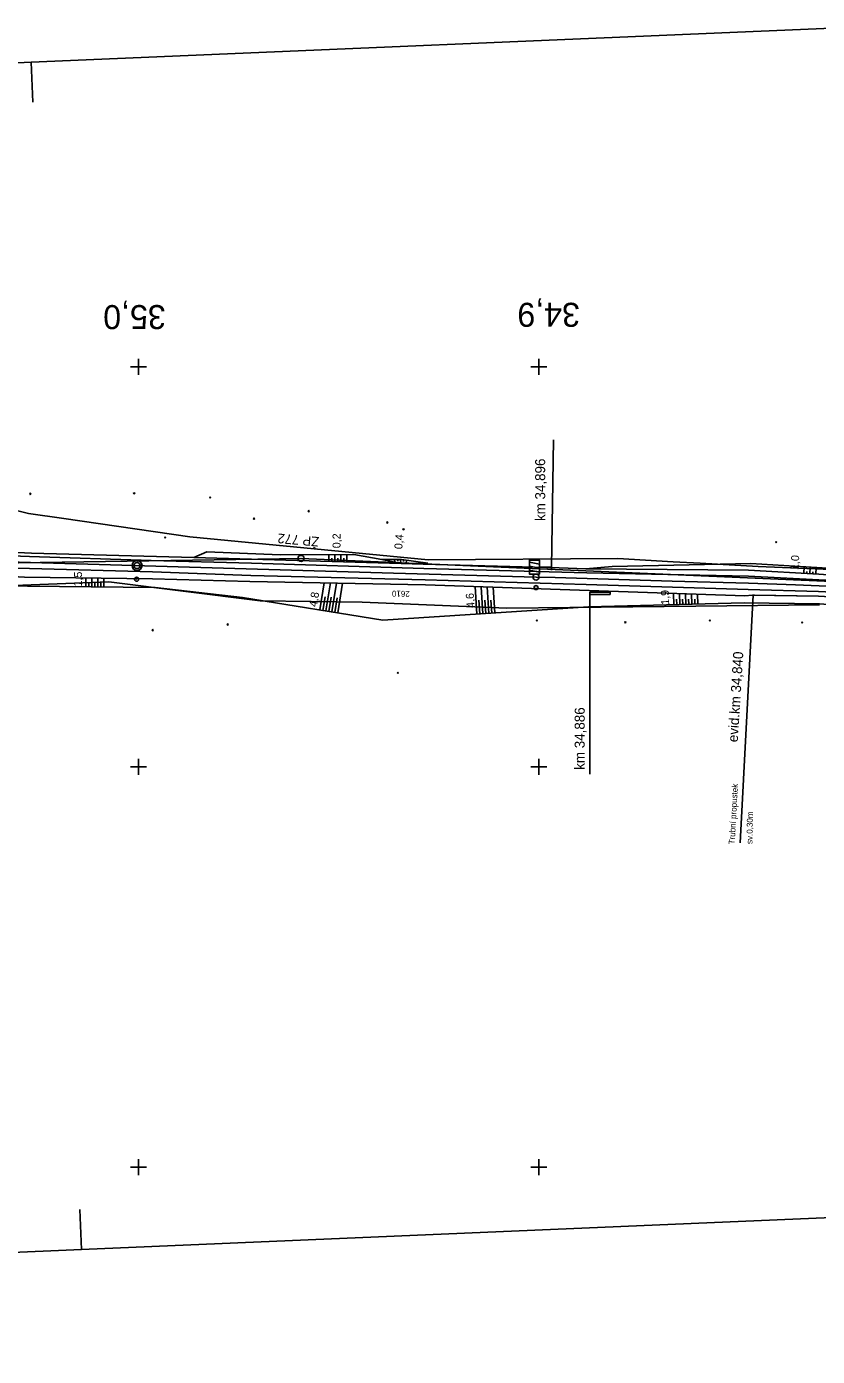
# Model space of a CAD drawing. Extents: x -806456 to -805395, y -1150847 to -1150506.
# Drawn here: x -805828 to -805630.4, y -1150847.3 to -1150515 of the extents above; entities that cross this region are included whole.
import ezdxf

# ---------------------------------------------------------------- set-up
doc = ezdxf.new("R2010")
doc.units = 0
for name, color, linetype in [('0381KM032-037P - Vrstva 1', 7, 'Continuous'), ('0381KM032-037P - Vrstva 19', 7, 'Continuous'), ('0381KM032-037P - Vrstva 4', 7, 'Continuous'), ('0381KM032-037P - Vrstva 48', 7, 'Continuous'), ('0381KM032-037P - Vrstva 49', 7, 'Continuous'), ('0381KM032-037P - Vrstva 57', 7, 'Continuous'), ('0381KM032-037P - Vrstva 7', 7, 'Continuous'), ('0381KM032-037P - Vrstva 9', 7, 'Continuous'), ('formát', 7, 'Continuous'), ('hran DP - hran DP', 7, 'Continuous'), ('krizky_1000 - Vrstva 1', 7, 'Continuous'), ('vyt_sit - polygon', 7, 'Continuous'), ('vyt_sit - stávající', 7, 'Continuous')]:
    doc.layers.add(name, color=color, linetype=linetype)

msp = doc.modelspace()

# ---------------------------------------------------------------- linework, layer by layer
at = {"layer": '0381KM032-037P - Vrstva 1'}
for points in [[(-805647.61, -1150654.06), (-805666.7, -1150653.55), (-805695.88, -1150652.69), (-805700.7, -1150652.54), (-805736.3, -1150651.55), (-805773.14, -1150650.48), (-805809.82, -1150649.4), (-805847.04, -1150648.36), (-805872.37, -1150647.65)], [(-805607.93, -1150656.05), (-805622.11, -1150655.05), (-805635.9, -1150654.45), (-805647.61, -1150654.06)]]:
    msp.add_lwpolyline(points, dxfattribs=at)
at = {"layer": '0381KM032-037P - Vrstva 19'}
for p, q in [((-805646.42, -1150657.11), (-805649.68, -1150718.98)), ((-805646.66, -1150657.1), (-805646.15, -1150657.11))]:
    msp.add_line(p, q, dxfattribs=at)
for points in [[(-805646.66, -1150657.1), (-805646.66, -1150657.1), (-805646.57, -1150657.13)], [(-805646.27, -1150657.1), (-805646.15, -1150657.11), (-805646.15, -1150657.11)]]:
    msp.add_lwpolyline(points, dxfattribs=at)
msp.add_ellipse((-805646.42, -1150657.11), major_axis=(0.15, 0.019), ratio=0.46044, start_param=6.207328, end_param=9.448235, dxfattribs=at)
at = {"layer": '0381KM032-037P - Vrstva 4'}
msp.add_line((-805728.9, -1150649.35), (-805734.36, -1150649.18), dxfattribs=at)
for points in [[(-805734.36, -1150649.18), (-805786.14, -1150647.68), (-805826.72, -1150646.54), (-805841.05, -1150645.92), (-805859.62, -1150645.3), (-805883.54, -1150644.38), (-805898.84, -1150644.02), (-805920.59, -1150645.08)], [(-805687.98, -1150651.47), (-805728.71, -1150650.4), (-805771.75, -1150649.09), (-805796.82, -1150648.44), (-805827.25, -1150647.42), (-805868.08, -1150645.94), (-805883.57, -1150645.79), (-805899.1, -1150645.56), (-805920.66, -1150646.24), (-805923.83, -1150646.61)], [(-805688.15, -1150654.42), (-805728.36, -1150653.2), (-805771.94, -1150652.19), (-805796.53, -1150651.28), (-805827.23, -1150650.42), (-805883.58, -1150648.86), (-805898.54, -1150648.68), (-805920.02, -1150649.65), (-805923.42, -1150649.97)], [(-805687.42, -1150655.93), (-805728.29, -1150654.47), (-805772.22, -1150653.64), (-805796.51, -1150653.02), (-805828.44, -1150652.6), (-805870.39, -1150650.22), (-805873.51, -1150650.39), (-805883.54, -1150650.55), (-805898.37, -1150650.08), (-805919.92, -1150650.63), (-805923.37, -1150650.9)], [(-805688.26, -1150650.5), (-805694.92, -1150650.2), (-805728.9, -1150649.35)], [(-805485.85, -1150681.76), (-805498.96, -1150678.92), (-805510.6, -1150675.66), (-805525.22, -1150671.48), (-805544.53, -1150665.72), (-805562.31, -1150661.11), (-805574.56, -1150658.15), (-805590.74, -1150655.42), (-805602.22, -1150654.14), (-805617.62, -1150652.74), (-805630.08, -1150651.83), (-805647.65, -1150650.8), (-805688.26, -1150650.5)], [(-805423.97, -1150686.92), (-805425.51, -1150687.49), (-805433.17, -1150688.49), (-805447.58, -1150687.79), (-805460.54, -1150686.52), (-805473.03, -1150684.97), (-805486, -1150682.53), (-805499.06, -1150679.64), (-805510.93, -1150676.58), (-805525.41, -1150672.29), (-805545.14, -1150666.47), (-805562.36, -1150661.85), (-805574.71, -1150659.28), (-805590.7, -1150656.46), (-805602.42, -1150654.96), (-805617.57, -1150653.8), (-805630.08, -1150653.28), (-805647.6, -1150652.35), (-805687.98, -1150651.47)], [(-805425.98, -1150691.47), (-805433.13, -1150691.22), (-805447.47, -1150690.71), (-805460.74, -1150689.57), (-805473.54, -1150687.87), (-805486.2, -1150685.62), (-805499.7, -1150682.42), (-805511.82, -1150679.35), (-805526.11, -1150675.23), (-805545.84, -1150669.48), (-805563.16, -1150664.96), (-805575.57, -1150662.2), (-805590.62, -1150659.46), (-805602.86, -1150658.06), (-805617.64, -1150656.78), (-805630.16, -1150656.16), (-805647.73, -1150655.65), (-805688.15, -1150654.42)], [(-805425.41, -1150692.47), (-805425.98, -1150691.47), (-805433.11, -1150692.35), (-805447.61, -1150691.82), (-805460.9, -1150690.59), (-805473.67, -1150688.98), (-805486.26, -1150686.57), (-805500.08, -1150683.65), (-805512.15, -1150680.12), (-805526.27, -1150676.26), (-805545.98, -1150670.57), (-805563.42, -1150665.87), (-805575.79, -1150663.12), (-805590.93, -1150660.59), (-805603.28, -1150659.09), (-805617.92, -1150657.97), (-805630.11, -1150657.32), (-805646.66, -1150657.1), (-805648.58, -1150657.2), (-805687.42, -1150655.93)]]:
    msp.add_lwpolyline(points, dxfattribs=at)
at = {"layer": '0381KM032-037P - Vrstva 48'}
for p, q in [((-805752.48, -1150648.66), (-805752.44, -1150646.97)), ((-805750.98, -1150648.7), (-805750.94, -1150646.96)), ((-805749.49, -1150648.74), (-805749.43, -1150646.96)), ((-805747.99, -1150648.79), (-805747.93, -1150646.95)), ((-805751.73, -1150648.68), (-805751.71, -1150647.82)), ((-805750.24, -1150648.72), (-805750.21, -1150647.84)), ((-805748.74, -1150648.77), (-805748.71, -1150647.86)), ((-805736.02, -1150648.12), (-805736.01, -1150648.83)), ((-805735.27, -1150648.12), (-805735.26, -1150648.56)), ((-805734.52, -1150648.12), (-805734.51, -1150649.15)), ((-805733.77, -1150648.2), (-805733.84, -1150648.69)), ((-805733.03, -1150648.31), (-805733.15, -1150649.17)), ((-805633.83, -1150651.61), (-805633.73, -1150649.96)), ((-805632.33, -1150651.7), (-805632.24, -1150650.05)), ((-805630.84, -1150651.79), (-805630.74, -1150650.15)), ((-805813.18, -1150654.95), (-805813.15, -1150652.8)), ((-805812.43, -1150654.96), (-805812.41, -1150653.89)), ((-805811.68, -1150654.97), (-805811.65, -1150652.82)), ((-805810.93, -1150654.98), (-805810.91, -1150653.91)), ((-805810.18, -1150654.99), (-805810.15, -1150652.84)), ((-805809.43, -1150654.99), (-805809.41, -1150653.92)), ((-805808.68, -1150655), (-805808.65, -1150652.86)), ((-805754.68, -1150660.78), (-805753.59, -1150653.99)), ((-805753.2, -1150661.01), (-805752.08, -1150654.02)), ((-805751.72, -1150661.25), (-805750.56, -1150654.05)), ((-805750.24, -1150661.49), (-805749.05, -1150654.08)), ((-805633.08, -1150651.65), (-805633.05, -1150651.16)), ((-805631.59, -1150651.74), (-805631.56, -1150651.25)), ((-805715.49, -1150661.81), (-805715.93, -1150654.91)), ((-805713.99, -1150661.71), (-805714.42, -1150654.97)), ((-805712.5, -1150661.62), (-805712.92, -1150655.02)), ((-805711, -1150661.52), (-805711.41, -1150655.07)), ((-805666.28, -1150659.46), (-805666.35, -1150656.62)), ((-805664.78, -1150659.42), (-805664.85, -1150656.67)), ((-805663.28, -1150659.38), (-805663.35, -1150656.72)), ((-805661.78, -1150659.34), (-805661.85, -1150656.77)), ((-805660.28, -1150659.3), (-805660.35, -1150656.81)), ((-805753.94, -1150660.89), (-805753.39, -1150657.45)), ((-805752.46, -1150661.13), (-805751.89, -1150657.58)), ((-805750.98, -1150661.37), (-805750.39, -1150657.72)), ((-805714.74, -1150661.76), (-805714.96, -1150658.35)), ((-805713.24, -1150661.67), (-805713.46, -1150658.33)), ((-805711.75, -1150661.57), (-805711.96, -1150658.31)), ((-805665.53, -1150659.44), (-805665.57, -1150658.04)), ((-805664.03, -1150659.4), (-805664.07, -1150658.04)), ((-805662.53, -1150659.36), (-805662.57, -1150658.05)), ((-805661.03, -1150659.32), (-805661.07, -1150658.05))]:
    msp.add_line(p, q, dxfattribs=at)
at = {"layer": '0381KM032-037P - Vrstva 49'}
for p, q in [((-805827.2, -1150631.55), (-805826.85, -1150631.9)), ((-805827.2, -1150631.9), (-805826.85, -1150631.55)), ((-805801.28, -1150631.44), (-805800.93, -1150631.8)), ((-805801.28, -1150631.8), (-805800.93, -1150631.44)), ((-805782.28, -1150632.48), (-805781.92, -1150632.83)), ((-805782.28, -1150632.83), (-805781.92, -1150632.48)), ((-805757.67, -1150635.89), (-805757.32, -1150636.25)), ((-805757.67, -1150636.25), (-805757.32, -1150635.89)), ((-805770.97, -1150637.78), (-805771.33, -1150638.14)), ((-805771.33, -1150637.78), (-805770.97, -1150638.13)), ((-805738.02, -1150638.73), (-805737.67, -1150639.09)), ((-805738.02, -1150639.09), (-805737.67, -1150638.73)), ((-805733.63, -1150640.45), (-805733.99, -1150640.81)), ((-805733.99, -1150640.45), (-805733.63, -1150640.81)), ((-805793.18, -1150642.5), (-805793.53, -1150642.85)), ((-805793.53, -1150642.5), (-805793.18, -1150642.85)), ((-805640.56, -1150643.67), (-805640.92, -1150644.02)), ((-805640.92, -1150643.67), (-805640.56, -1150644.02)), ((-805700.33, -1150663.23), (-805700.68, -1150663.59)), ((-805700.68, -1150663.23), (-805700.33, -1150663.58)), ((-805678.21, -1150663.68), (-805678.56, -1150664.04)), ((-805678.56, -1150663.69), (-805678.21, -1150664.04)), ((-805657.1, -1150663.22), (-805657.46, -1150663.57)), ((-805657.46, -1150663.22), (-805657.1, -1150663.57)), ((-805634.06, -1150663.7), (-805634.41, -1150664.05)), ((-805634.41, -1150663.7), (-805634.05, -1150664.05)), ((-805796.29, -1150665.66), (-805796.64, -1150666.01)), ((-805796.64, -1150665.66), (-805796.29, -1150666.01)), ((-805777.92, -1150664.26), (-805777.56, -1150664.61)), ((-805777.56, -1150664.26), (-805777.91, -1150664.61)), ((-805735.04, -1150676.33), (-805735.39, -1150676.68)), ((-805735.39, -1150676.33), (-805735.04, -1150676.68))]:
    msp.add_line(p, q, dxfattribs=at)
for points in [[(-805786.14, -1150647.68), (-805826.72, -1150646.54), (-805841.05, -1150645.92)], [(-805786.14, -1150647.68), (-805782.97, -1150646.21), (-805764.63, -1150647), (-805746.23, -1150646.95), (-805739.21, -1150648.13), (-805734.36, -1150649.18), (-805727.71, -1150649.08)], [(-805687.42, -1150655.93), (-805728.29, -1150654.47), (-805772.22, -1150653.64), (-805796.51, -1150653.02), (-805828.44, -1150652.6), (-805870.39, -1150650.22)], [(-805687.58, -1150660.02), (-805738.95, -1150663.31), (-805774.06, -1150657.65), (-805795.8, -1150655.14), (-805835.84, -1150654.7), (-805870.36, -1150656.71), (-805870.39, -1150650.22)], [(-805734.36, -1150649.18), (-805786.14, -1150647.68)], [(-805727.71, -1150649.08), (-805734.34, -1150648.12), (-805739.21, -1150648.13)], [(-805602.19, -1150651.94), (-805630.54, -1150650.16), (-805647.04, -1150649.14), (-805681.66, -1150649.9), (-805688.26, -1150650.5)], [(-805423.97, -1150686.92), (-805433.1, -1150687.91), (-805447.34, -1150686.91), (-805460.49, -1150686.09), (-805485.85, -1150681.76), (-805498.96, -1150678.92), (-805510.6, -1150675.66), (-805525.22, -1150671.48), (-805544.53, -1150665.72), (-805562.31, -1150661.11), (-805571.99, -1150658.79), (-805574.56, -1150658.15), (-805590.74, -1150655.42), (-805602.22, -1150654.14), (-805617.62, -1150652.74), (-805630.08, -1150651.83), (-805647.65, -1150650.8), (-805688.26, -1150650.5)], [(-805425.41, -1150692.47), (-805425.98, -1150691.47), (-805433.11, -1150692.35), (-805447.61, -1150691.82), (-805460.9, -1150690.59), (-805473.67, -1150688.98), (-805486.26, -1150686.57), (-805500.08, -1150683.65), (-805512.15, -1150680.12), (-805526.27, -1150676.26), (-805545.98, -1150670.57), (-805563.42, -1150665.87), (-805575.79, -1150663.12), (-805590.93, -1150660.59), (-805603.28, -1150659.09), (-805617.92, -1150657.97), (-805630.11, -1150657.32), (-805646.15, -1150657.11), (-805646.27, -1150657.1), (-805646.57, -1150657.13), (-805646.66, -1150657.1), (-805648.58, -1150657.2), (-805687.42, -1150655.93)], [(-805428.8, -1150698.61), (-805426.99, -1150695.45), (-805434.79, -1150695.76), (-805452.59, -1150694.8), (-805474.79, -1150691.73), (-805486.9, -1150690.07), (-805513.13, -1150683.83), (-805526.69, -1150679.91), (-805538.18, -1150675.92), (-805547.05, -1150672.92), (-805563.97, -1150668.42), (-805576.87, -1150665.35), (-805586.81, -1150663.24), (-805590.73, -1150662.74), (-805601.92, -1150661.35), (-805629.88, -1150659.22), (-805648.74, -1150658.99), (-805687.58, -1150660.02)]]:
    msp.add_lwpolyline(points, dxfattribs=at)
at = {"layer": '0381KM032-037P - Vrstva 7'}
for p, q in [((-805696.85, -1150650.05), (-805696.3, -1150618.26)), ((-805699.85, -1150649.3), (-805702.35, -1150648.8)), ((-805702.35, -1150649.8), (-805699.85, -1150650.3)), ((-805696.85, -1150650.8), (-805696.85, -1150649.3)), ((-805800.52, -1150653.09), (-805800.42, -1150653.09)), ((-805699.85, -1150651.3), (-805702.35, -1150650.8)), ((-805700.75, -1150655.18), (-805700.65, -1150655.18))]:
    msp.add_line(p, q, dxfattribs=at)
msp.add_lwpolyline([(-805696.85, -1150650.05), (-805699.85, -1150650.05), (-805699.85, -1150648.3), (-805702.35, -1150648.3), (-805702.35, -1150651.8), (-805699.85, -1150651.8), (-805699.85, -1150650.05)], dxfattribs=at)
for centre, radius in [((-805800.37, -1150649.68), 1.25), ((-805800.37, -1150649.68), 0.752), ((-805800.47, -1150653.09), 0.5), ((-805700.7, -1150652.54), 0.75), ((-805700.7, -1150655.18), 0.5)]:
    msp.add_circle(centre, radius, dxfattribs=at)
at = {"layer": '0381KM032-037P - Vrstva 9'}
for p, q in [((-805682.22, -1150656.32), (-805687.22, -1150656.31)), ((-805687.22, -1150656.31), (-805687.22, -1150656.91)), ((-805687.22, -1150656.61), (-805687.22, -1150701.82)), ((-805687.22, -1150656.91), (-805682.22, -1150656.92)), ((-805687.22, -1150656.91), (-805687.22, -1150657.51)), ((-805682.22, -1150656.92), (-805682.22, -1150656.32))]:
    msp.add_line(p, q, dxfattribs=at)
at = {"layer": 'formát'}
for p, q in [((-805617.02, -1150514.97), (-805826.83, -1150523.88)), ((-805826.83, -1150523.88), (-806456.26, -1150550.6)), ((-805826.83, -1150523.88), (-805826.4, -1150533.87)), ((-805814.66, -1150810.62), (-805814.23, -1150820.61)), ((-805604.42, -1150811.7), (-805814.23, -1150820.61)), ((-805814.23, -1150820.61), (-806443.66, -1150847.33))]:
    msp.add_line(p, q, dxfattribs=at)
at = {"layer": 'hran DP - hran DP'}
for p, q in [((-805845.04, -1150632.24), (-805827.46, -1150636.65)), ((-805827.46, -1150636.65), (-805818.65, -1150637.92)), ((-805818.65, -1150637.92), (-805787.18, -1150642.48)), ((-805787.18, -1150642.48), (-805727.67, -1150648.26)), ((-805727.67, -1150648.26), (-805680.28, -1150647.93)), ((-805680.28, -1150647.93), (-805666.44, -1150648.72)), ((-805666.44, -1150648.72), (-805659.71, -1150649.1)), ((-805659.71, -1150649.1), (-805655.39, -1150649.35)), ((-805655.39, -1150649.35), (-805645.21, -1150649.93)), ((-805645.21, -1150649.93), (-805611.34, -1150651.29)), ((-805807.41, -1150653.77), (-805838.22, -1150654.94)), ((-805769.65, -1150658.51), (-805807.41, -1150653.77)), ((-805744.09, -1150658.84), (-805769.65, -1150658.51)), ((-805707.95, -1150660.33), (-805744.09, -1150658.84)), ((-805660.75, -1150659.79), (-805707.95, -1150660.33)), ((-805629.87, -1150659.45), (-805660.75, -1150659.79))]:
    msp.add_line(p, q, dxfattribs=at)
at = {"layer": 'krizky_1000 - Vrstva 1'}
for points in [[(-805802, -1150600), (-805798, -1150600)], [(-805800, -1150598), (-805800, -1150602)], [(-805702, -1150600), (-805698, -1150600)], [(-805700, -1150598), (-805700, -1150602)], [(-805802, -1150700), (-805798, -1150700)], [(-805800, -1150698), (-805800, -1150702)], [(-805702, -1150700), (-805698, -1150700)], [(-805700, -1150698), (-805700, -1150702)], [(-805802, -1150800), (-805798, -1150800)], [(-805800, -1150798), (-805800, -1150802)], [(-805702, -1150800), (-805698, -1150800)], [(-805700, -1150798), (-805700, -1150802)]]:
    msp.add_lwpolyline(points, dxfattribs=at)
at = {"layer": 'vyt_sit - polygon'}
for p, q in [((-805901.58, -1150650.08), (-805759.38, -1150647.88)), ((-805759.38, -1150647.88), (-805585.64, -1150655.42))]:
    msp.add_line(p, q, dxfattribs=at)
at = {"layer": 'vyt_sit - stávající'}
msp.add_line((-805759.43, -1150647.88), (-805759.33, -1150647.88), dxfattribs=at)
msp.add_circle((-805759.38, -1150647.88), 0.756, dxfattribs=at)

# ---------------------------------------------------------------- texts
at = {"layer": '0381KM032-037P - Vrstva 19'}
for s, height, rotation, p in [('evid.km 34,840', 2.5, 86.4544, (-805650.31, -1150693.88)), ('Trubní propustek', 1.5, 86.8495, (-805651.08, -1150719.38)), ('sv.0,30m', 1.5, 88.8723, (-805646.65, -1150719.28))]:
    msp.add_text(s, height=height, rotation=rotation, dxfattribs=at).set_placement(p)
at = {"layer": '0381KM032-037P - Vrstva 48'}
for s, rotation, p in [('0,2', 90.1588, (-805749.52, -1150645.34)), ('0,4', 85.1177, (-805734.12, -1150645.65)), ('1,0', 86.4602, (-805635.16, -1150650.83)), ('1,5', 89.3704, (-805814.15, -1150654.92)), ('4,8', 80.8487, (-805755.45, -1150660.12)), ('4,6', 93.6586, (-805716.04, -1150660.2)), ('1,9', 91.5281, (-805667.43, -1150659.46))]:
    msp.add_text(s, height=2, rotation=rotation, dxfattribs=at).set_placement(p)
at = {"layer": '0381KM032-037P - Vrstva 57'}
msp.add_text('2610', height=1.5, rotation=179.2665, dxfattribs=at).set_placement((-805732.22, -1150656.01))
at = {"layer": '0381KM032-037P - Vrstva 7'}
for s, height, rotation, p in [('35,0', 6, 180, (-805793.2, -1150584.57)), ('34,9', 6, 180, (-805689.73, -1150584)), ('km 34,896', 2.5, 90, (-805698.41, -1150638.55))]:
    msp.add_text(s, height=height, rotation=rotation, dxfattribs=at).set_placement(p)
at = {"layer": '0381KM032-037P - Vrstva 9'}
msp.add_text('km 34,886', height=2.5, rotation=89.869, dxfattribs=at).set_placement((-805688.57, -1150700.72))
at = {"layer": 'vyt_sit - stávající'}
msp.add_text('ŽP 772', height=2.4, rotation=175, dxfattribs=at).set_placement((-805754.82, -1150642.56))

doc.saveas('drawing.dxf')
